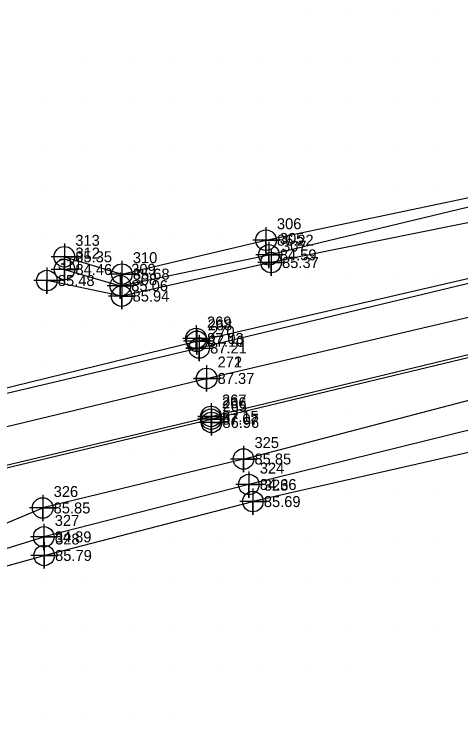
# Model space of a CAD drawing. Extents: x 1988140 to 1988766, y 249950 to 250250.
# Drawn here: x 1988543.5 to 1988645.4, y 250020 to 250180 of the extents above; entities that cross this region are included whole.
import ezdxf

# ---------------------------------------------------------------- set-up
doc = ezdxf.new("R2010")
doc.units = 0
for name, color, linetype in [('Exist DTM Breakline', 7, 'Continuous'), ('Exist DTM Breakline Cogo Elevation', 7, 'Continuous'), ('Exist DTM Breakline Cogo Number', 7, 'Continuous'), ('Exist DTM Breakline Cogo Point CELL', 7, 'Continuous'), ('Exist DTM Crownline', 7, 'Continuous'), ('Exist DTM Crownline Cogo Elevation', 7, 'Continuous'), ('Exist DTM Crownline Cogo Number', 7, 'Continuous'), ('Exist DTM Crownline Cogo Point CELL', 7, 'Continuous'), ('Exist DTM QL2 LIDAR Elevation Point', 7, 'Continuous'), ('Exist DTM Regular Point CELL', 7, 'Continuous'), ('Exist DTM Regular Point Cogo Elevation', 7, 'Continuous'), ('Exist DTM Regular Point Cogo Number', 7, 'Continuous'), ('Exist Roads EOP', 7, 'Continuous'), ('Exist Roads EOP Cogo Elevation', 7, 'Continuous'), ('Exist Roads EOP Cogo Number', 7, 'Continuous'), ('Exist Roads EOP Cogo Point CELL', 7, 'Continuous'), ('Exist Roads EOT', 7, 'Continuous'), ('Exist Roads EOT Cogo Elevation', 7, 'Continuous'), ('Exist Roads EOT Cogo Number', 7, 'Continuous'), ('Exist Roads EOT Cogo Point CELL', 7, 'Continuous')]:
    doc.layers.add(name, color=color, linetype=linetype)

msp = doc.modelspace()

# ---------------------------------------------------------------- linework, layer by layer
at = {"layer": 'Exist DTM Breakline'}
for p, q in [((1988595.8486, 250078.4284), (1988659.2567, 250095.0375)), ((1988514.4933, 250052.5489), (1988550.0675, 250067.2509)), ((1988550.3991, 250056.4169), (1988597.985, 250068.7119)), ((1988515.8353, 250049.9896), (1988550.3151, 250060.6577)), ((1988517.2677, 250047.0884), (1988550.3991, 250056.4169))]:
    msp.add_line(p, q, dxfattribs=at)
for points in [[(1988555.0044, 250124.5902), (1988568.1239, 250120.6374), (1988600.9717, 250128.3768), (1988650.8805, 250138.872), (1988697.6656, 250149.8966), (1988743.3182, 250160.187)], [(1988555.0333, 250121.6898), (1988567.7596, 250117.9867), (1988601.6281, 250125.0214), (1988650.6465, 250136.8359), (1988698.1189, 250148.056), (1988743.6869, 250158.1958)], [(1988745.028, 250154.0761), (1988698.9071, 250144.5644), (1988652.2033, 250133.4001), (1988602.1386, 250123.2677), (1988568.0707, 250115.6185), (1988551.0253, 250119.1644)], [(1988753.9895, 250110.2756), (1988710.141, 250098.807), (1988660.1934, 250088.2068), (1988597.0615, 250072.5993), (1988550.3151, 250060.6577)], [(1988661.2286, 250083.135), (1988597.985, 250068.7119)], [(1988595.8486, 250078.4284), (1988550.0675, 250067.2509)]]:
    msp.add_lwpolyline(points, dxfattribs=at)
at = {"layer": 'Exist DTM Breakline Cogo Point CELL'}
for points in [[(1988600.9717, 250131.3768), (1988600.9717, 250125.3768), (1988600.9717, 250128.3768), (1988603.9717, 250128.3768), (1988597.9717, 250128.3768)], [(1988601.6281, 250128.0214), (1988601.6281, 250122.0214), (1988601.6281, 250125.0214), (1988604.6281, 250125.0214), (1988598.6281, 250125.0214)], [(1988555.0044, 250127.5902), (1988555.0044, 250121.5902), (1988555.0044, 250124.5902), (1988558.0044, 250124.5902), (1988552.0044, 250124.5902)], [(1988602.1386, 250126.2677), (1988602.1386, 250120.2677), (1988602.1386, 250123.2677), (1988605.1386, 250123.2677), (1988599.1386, 250123.2677)], [(1988555.0333, 250124.6898), (1988555.0333, 250118.6898), (1988555.0333, 250121.6898), (1988558.0333, 250121.6898), (1988552.0333, 250121.6898)], [(1988568.1239, 250123.6374), (1988568.1239, 250117.6374), (1988568.1239, 250120.6374), (1988571.1239, 250120.6374), (1988565.1239, 250120.6374)], [(1988551.0253, 250122.1644), (1988551.0253, 250116.1644), (1988551.0253, 250119.1644), (1988554.0253, 250119.1644), (1988548.0253, 250119.1644)], [(1988567.7596, 250120.9867), (1988567.7596, 250114.9867), (1988567.7596, 250117.9867), (1988570.7596, 250117.9867), (1988564.7596, 250117.9867)], [(1988568.0707, 250118.6185), (1988568.0707, 250112.6185), (1988568.0707, 250115.6185), (1988571.0707, 250115.6185), (1988565.0707, 250115.6185)], [(1988595.8486, 250081.4284), (1988595.8486, 250075.4284), (1988595.8486, 250078.4284), (1988598.8486, 250078.4284), (1988592.8486, 250078.4284)], [(1988597.0615, 250075.5993), (1988597.0615, 250069.5993), (1988597.0615, 250072.5993), (1988600.0615, 250072.5993), (1988594.0615, 250072.5993)], [(1988597.985, 250071.7119), (1988597.985, 250065.7119), (1988597.985, 250068.7119), (1988600.985, 250068.7119), (1988594.985, 250068.7119)], [(1988550.0675, 250070.2509), (1988550.0675, 250064.2509), (1988550.0675, 250067.2509), (1988553.0675, 250067.2509), (1988547.0675, 250067.2509)], [(1988550.3151, 250063.6577), (1988550.3151, 250057.6577), (1988550.3151, 250060.6577), (1988553.3151, 250060.6577), (1988547.3151, 250060.6577)], [(1988550.3991, 250059.4169), (1988550.3991, 250053.4169), (1988550.3991, 250056.4169), (1988553.3991, 250056.4169), (1988547.3991, 250056.4169)]]:
    msp.add_lwpolyline(points, dxfattribs=at)
for centre in [(1988600.9717, 250128.3768), (1988555.0044, 250124.5902), (1988601.6281, 250125.0214), (1988602.1386, 250123.2677), (1988555.0333, 250121.6898), (1988568.1239, 250120.6374), (1988551.0253, 250119.1644), (1988567.7596, 250117.9867), (1988568.0707, 250115.6185), (1988595.8486, 250078.4284), (1988597.0615, 250072.5993), (1988597.985, 250068.7119), (1988550.0675, 250067.2509), (1988550.3151, 250060.6577), (1988550.3991, 250056.4169)]:
    msp.add_circle(centre, 2.344, dxfattribs=at)
at = {"layer": 'Exist DTM Crownline'}
for points in [[(1988586.896, 250096.6857), (1988587.4445, 250096.8162), (1988723.0829, 250128.6331), (1988749.0571, 250134.715)], [(1988476.6655, 250070.3758), (1988523.8279, 250081.5102), (1988587.4445, 250096.8162)]]:
    msp.add_lwpolyline(points, dxfattribs=at)
at = {"layer": 'Exist DTM Crownline Cogo Point CELL'}
msp.add_lwpolyline([(1988587.4445, 250099.8162), (1988587.4445, 250093.8162), (1988587.4445, 250096.8162), (1988590.4445, 250096.8162), (1988584.4445, 250096.8162)], dxfattribs=at)
msp.add_circle((1988587.4445, 250096.8162), 2.344, dxfattribs=at)
at = {"layer": 'Exist DTM QL2 LIDAR Elevation Point'}
for p, q in [((1988610, 250180), (1988610, 250180)), ((1988620, 250180), (1988620, 250180)), ((1988630, 250180), (1988630, 250180)), ((1988640, 250180), (1988640, 250180)), ((1988560, 250170), (1988560, 250170)), ((1988570, 250170), (1988570, 250170)), ((1988580, 250170), (1988580, 250170)), ((1988590, 250170), (1988590, 250170)), ((1988600, 250170), (1988600, 250170)), ((1988610, 250170), (1988610, 250170)), ((1988620, 250170), (1988620, 250170)), ((1988630, 250170), (1988630, 250170)), ((1988640, 250170), (1988640, 250170)), ((1988550, 250160), (1988550, 250160)), ((1988560, 250160), (1988560, 250160)), ((1988570, 250160), (1988570, 250160)), ((1988580, 250160), (1988580, 250160)), ((1988590, 250160), (1988590, 250160)), ((1988600, 250160), (1988600, 250160)), ((1988610, 250160), (1988610, 250160)), ((1988620, 250160), (1988620, 250160)), ((1988630, 250160), (1988630, 250160)), ((1988640, 250160), (1988640, 250160)), ((1988550, 250150), (1988550, 250150)), ((1988560, 250150), (1988560, 250150)), ((1988570, 250150), (1988570, 250150)), ((1988580, 250150), (1988580, 250150)), ((1988590, 250150), (1988590, 250150)), ((1988600, 250150), (1988600, 250150)), ((1988610, 250150), (1988610, 250150)), ((1988620, 250150), (1988620, 250150)), ((1988630, 250150), (1988630, 250150)), ((1988640, 250150), (1988640, 250150)), ((1988550, 250140), (1988550, 250140)), ((1988560, 250140), (1988560, 250140)), ((1988570, 250140), (1988570, 250140)), ((1988580, 250140), (1988580, 250140)), ((1988590, 250140), (1988590, 250140)), ((1988600, 250140), (1988600, 250140)), ((1988610, 250140), (1988610, 250140)), ((1988620, 250140), (1988620, 250140)), ((1988630, 250140), (1988630, 250140)), ((1988640, 250140), (1988640, 250140)), ((1988550, 250130), (1988550, 250130)), ((1988560, 250130), (1988560, 250130)), ((1988570, 250130), (1988570, 250130)), ((1988580, 250130), (1988580, 250130)), ((1988590, 250130), (1988590, 250130)), ((1988600, 250130), (1988600, 250130)), ((1988640, 250130), (1988640, 250130)), ((1988600, 250120), (1988600, 250120)), ((1988610, 250120), (1988610, 250120)), ((1988620, 250120), (1988620, 250120)), ((1988630, 250120), (1988630, 250120)), ((1988640, 250120), (1988640, 250120)), ((1988550, 250110), (1988550, 250110)), ((1988560, 250110), (1988560, 250110)), ((1988570, 250110), (1988570, 250110)), ((1988580, 250110), (1988580, 250110)), ((1988590, 250110), (1988590, 250110)), ((1988550, 250100), (1988550, 250100)), ((1988640, 250100), (1988640, 250100)), ((1988600, 250090), (1988600, 250090)), ((1988610, 250090), (1988610, 250090)), ((1988620, 250090), (1988620, 250090)), ((1988630, 250090), (1988630, 250090)), ((1988640, 250090), (1988640, 250090)), ((1988570, 250080), (1988570, 250080)), ((1988580, 250080), (1988580, 250080)), ((1988590, 250080), (1988590, 250080)), ((1988550, 250070), (1988550, 250070)), ((1988560, 250070), (1988560, 250070)), ((1988610, 250070), (1988610, 250070)), ((1988620, 250070), (1988620, 250070)), ((1988630, 250070), (1988630, 250070)), ((1988640, 250070), (1988640, 250070)), ((1988570, 250060), (1988570, 250060)), ((1988580, 250060), (1988580, 250060)), ((1988590, 250060), (1988590, 250060)), ((1988600, 250060), (1988600, 250060)), ((1988610, 250060), (1988610, 250060)), ((1988620, 250060), (1988620, 250060)), ((1988630, 250060), (1988630, 250060)), ((1988640, 250060), (1988640, 250060)), ((1988550, 250050), (1988550, 250050)), ((1988560, 250050), (1988560, 250050)), ((1988570, 250050), (1988570, 250050)), ((1988580, 250050), (1988580, 250050)), ((1988590, 250050), (1988590, 250050)), ((1988600, 250050), (1988600, 250050)), ((1988610, 250050), (1988610, 250050)), ((1988620, 250050), (1988620, 250050)), ((1988630, 250050), (1988630, 250050)), ((1988640, 250050), (1988640, 250050)), ((1988550, 250040), (1988550, 250040)), ((1988560, 250040), (1988560, 250040)), ((1988570, 250040), (1988570, 250040)), ((1988580, 250040), (1988580, 250040)), ((1988590, 250040), (1988590, 250040)), ((1988600, 250040), (1988600, 250040)), ((1988610, 250040), (1988610, 250040)), ((1988620, 250040), (1988620, 250040)), ((1988630, 250040), (1988630, 250040)), ((1988640, 250040), (1988640, 250040)), ((1988550, 250030), (1988550, 250030)), ((1988560, 250030), (1988560, 250030)), ((1988570, 250030), (1988570, 250030)), ((1988580, 250030), (1988580, 250030)), ((1988590, 250030), (1988590, 250030)), ((1988600, 250030), (1988600, 250030)), ((1988610, 250030), (1988610, 250030)), ((1988620, 250030), (1988620, 250030)), ((1988550, 250020), (1988550, 250020)), ((1988560, 250020), (1988560, 250020)), ((1988570, 250020), (1988570, 250020)), ((1988580, 250020), (1988580, 250020))]:
    msp.add_line(p, q, dxfattribs=at)
at = {"layer": 'Exist DTM Regular Point CELL'}
for points in [[(1988585.0206, 250108.9413), (1988585.0206, 250102.9413), (1988585.0206, 250105.9413), (1988588.0206, 250105.9413), (1988582.0206, 250105.9413)], [(1988588.55, 250089.7797), (1988588.55, 250083.7797), (1988588.55, 250086.7797), (1988591.55, 250086.7797), (1988585.55, 250086.7797)]]:
    msp.add_lwpolyline(points, dxfattribs=at)
for centre in [(1988585.0206, 250105.9413), (1988588.55, 250086.7797)]:
    msp.add_circle(centre, 2.344, dxfattribs=at)
at = {"layer": 'Exist Roads EOP'}
for points in [[(1988474.5186, 250079.1384), (1988520.6371, 250089.4794), (1988585.1885, 250105.299), (1988653.4927, 250121.1544), (1988721.8388, 250137.0511), (1988746.7518, 250142.7981)], [(1988478.7113, 250061.1525), (1988526.3961, 250072.7689), (1988588.4517, 250087.5135), (1988658.4677, 250104.3569), (1988725.1723, 250119.8591), (1988750.1331, 250125.8579)]]:
    msp.add_lwpolyline(points, dxfattribs=at)
at = {"layer": 'Exist Roads EOP Cogo Point CELL'}
for points in [[(1988585.1885, 250108.299), (1988585.1885, 250102.299), (1988585.1885, 250105.299), (1988588.1885, 250105.299), (1988582.1885, 250105.299)], [(1988588.4517, 250090.5135), (1988588.4517, 250084.5135), (1988588.4517, 250087.5135), (1988591.4517, 250087.5135), (1988585.4517, 250087.5135)]]:
    msp.add_lwpolyline(points, dxfattribs=at)
for centre in [(1988585.1885, 250105.299), (1988588.4517, 250087.5135)]:
    msp.add_circle(centre, 2.344, dxfattribs=at)
at = {"layer": 'Exist Roads EOT'}
for points in [[(1988747.017, 250141.8392), (1988721.8571, 250135.9434), (1988653.8188, 250120.1043), (1988585.7363, 250103.7612), (1988520.8576, 250088.4105), (1988474.7146, 250078.1173)], [(1988478.5507, 250062.0221), (1988526.3466, 250073.3488), (1988588.4376, 250088.1415), (1988658.1757, 250104.9714), (1988725.0188, 250120.3526), (1988749.8922, 250126.2558)]]:
    msp.add_lwpolyline(points, dxfattribs=at)
at = {"layer": 'Exist Roads EOT Cogo Point CELL'}
for points in [[(1988585.7363, 250106.7612), (1988585.7363, 250100.7612), (1988585.7363, 250103.7612), (1988582.7363, 250103.7612), (1988588.7363, 250103.7612)], [(1988587.4445, 250099.8162), (1988587.4445, 250093.8162), (1988587.4445, 250096.8162), (1988584.4445, 250096.8162), (1988590.4445, 250096.8162)], [(1988588.4376, 250091.1415), (1988588.4376, 250085.1415), (1988588.4376, 250088.1415), (1988585.4376, 250088.1415), (1988591.4376, 250088.1415)]]:
    msp.add_lwpolyline(points, dxfattribs=at)
for centre in [(1988585.7363, 250103.7612), (1988587.4445, 250096.8162), (1988588.4376, 250088.1415)]:
    msp.add_circle(centre, 2.344, dxfattribs=at)

# ---------------------------------------------------------------- texts
at = {"layer": 'Exist DTM Breakline Cogo Elevation'}
for s, p in [('86.22', (1988603.4717, 250127.1268)), ('85.35', (1988557.5044, 250123.3402)), ('84.59', (1988604.1281, 250123.7714)), ('85.37', (1988604.6386, 250122.0177)), ('84.46', (1988557.5333, 250120.4398)), ('85.68', (1988570.6239, 250119.3874)), ('85.48', (1988553.5253, 250117.9144)), ('85.06', (1988570.2596, 250116.7367)), ('85.94', (1988570.5707, 250114.3685)), ('85.85', (1988598.3486, 250077.1784)), ('84.66', (1988599.5615, 250071.3493)), ('85.69', (1988600.485, 250067.4619)), ('85.85', (1988552.5675, 250066.0009)), ('84.89', (1988552.8151, 250059.4077)), ('85.79', (1988552.8991, 250055.1669))]:
    msp.add_text(s, height=2.5, dxfattribs=at).set_placement(p)
at = {"layer": 'Exist DTM Breakline Cogo Number'}
for s, p in [('306', (1988603.4717, 250130.8768)), ('313', (1988557.5044, 250127.0902)), ('305', (1988604.1281, 250127.5214)), ('307', (1988604.6386, 250125.7677)), ('312', (1988557.5333, 250124.1898)), ('310', (1988570.6239, 250123.1374)), ('311', (1988553.5253, 250121.6644)), ('309', (1988570.2596, 250120.4867)), ('308', (1988570.5707, 250118.1185)), ('325', (1988598.3486, 250080.9284)), ('324', (1988599.5615, 250075.0993)), ('323', (1988600.485, 250071.2119)), ('326', (1988552.5675, 250069.7509)), ('327', (1988552.8151, 250063.1577)), ('328', (1988552.8991, 250058.9169))]:
    msp.add_text(s, height=2.5, dxfattribs=at).set_placement(p)
at = {"layer": 'Exist DTM Crownline Cogo Elevation'}
msp.add_text('87.37', height=2.5, dxfattribs=at).set_placement((1988589.9445, 250095.5662))
at = {"layer": 'Exist DTM Crownline Cogo Number'}
msp.add_text('272', height=2.5, dxfattribs=at).set_placement((1988589.9445, 250099.3162))
at = {"layer": 'Exist DTM Regular Point Cogo Elevation'}
for s, p in [('87.03', (1988587.5206, 250104.6913)), ('86.96', (1988591.05, 250085.5297))]:
    msp.add_text(s, height=2.5, dxfattribs=at).set_placement(p)
at = {"layer": 'Exist DTM Regular Point Cogo Number'}
for s, p in [('269', (1988587.5206, 250108.4413)), ('265', (1988591.05, 250089.2797))]:
    msp.add_text(s, height=2.5, dxfattribs=at).set_placement(p)
at = {"layer": 'Exist Roads EOP Cogo Elevation'}
for s, p in [('87.10', (1988587.6885, 250104.049)), ('87.07', (1988590.9517, 250086.2635))]:
    msp.add_text(s, height=2.5, dxfattribs=at).set_placement(p)
at = {"layer": 'Exist Roads EOP Cogo Number'}
for s, p in [('268', (1988587.6885, 250107.799)), ('266', (1988590.9517, 250090.0135))]:
    msp.add_text(s, height=2.5, dxfattribs=at).set_placement(p)
at = {"layer": 'Exist Roads EOT Cogo Elevation'}
for s, p in [('87.21', (1988588.2363, 250102.5112)), ('87.37', (1988589.9445, 250095.5662)), ('87.15', (1988590.9376, 250086.8915))]:
    msp.add_text(s, height=2.5, dxfattribs=at).set_placement(p)
at = {"layer": 'Exist Roads EOT Cogo Number'}
for s, p in [('270', (1988588.2363, 250106.2612)), ('271', (1988589.9445, 250099.3162)), ('267', (1988590.9376, 250090.6415))]:
    msp.add_text(s, height=2.5, dxfattribs=at).set_placement(p)

doc.saveas('drawing.dxf')
